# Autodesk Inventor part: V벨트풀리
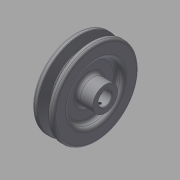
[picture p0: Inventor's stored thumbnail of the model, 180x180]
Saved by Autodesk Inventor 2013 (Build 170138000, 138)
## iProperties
Created: 2015-11
Part Number: V벨트풀리
Material: 강철, 탄소
Document SubType Name: Modeling
Designer: mduedu
Density: 1 g/cm^3
Author: mduedu
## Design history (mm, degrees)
sketch "스케치1"
  geometry: L1 (-9.5, 0)-(9.5, 0); L2 (0, 0)-(0, 37.7); L3 (-4.825, 37.7)-(-9.5, 37.7); L4 (-9.5, 37.7)-(-9.5, 0); L5 (0, 28.7)-(-2.074, 28.7); L6 (-2.074, 28.7)-(-4.825, 37.7); L7 (4.825, 37.7)-(9.5, 37.7); L8 (9.5, 37.7)-(9.5, 0); L9 (0, 28.7)-(2.074, 28.7); L10 (2.074, 28.7)-(4.825, 37.7); L11 (-9.5, 35)-(9.5, 35); 3 further points
  constraints: 22 end point, 7 point on line, 4 perpendicular, 3 symmetric about line, 1 coincident, 1 horizontal, 1 horizontal alignment, 1 midpoint, 1 vertical
  dimensions: "d0" = 19 distance of L1.start L1.end; "d2" = 75.4 diameter of L2.end L1 (derived); "d3" = 34 deg angle of L10 L6; "d4" = 6.3 distance between parallel lines of L11 L9; "d5" = 2.7 distance between parallel lines of L7 L11; "d6" = 8 distance of point (4, 35) point (-4, 35); "d7" = 70 diameter of L11 L1
revolve "회전1" sketch "스케치1" stored, may be unused: angle "d8" = 90 deg
sketch "스케치2"
  geometry: C1 r 24 at (0, 0); C2 r 11 at (0, 0); 1 further point
  constraints: 2 centre point, 2 coincident
  dimensions: "d9" = 48 diameter of C1; "d10" = 22 diameter of C2
extrude "돌출1" cut sketch "스케치2" distance "d11" = 6; taper "d12" = 0 deg
extrude "돌출3" join sketch "스케치2" distance "d37" = 8; taper "d38" = 0 deg
fillet "모깎기1" dims "d13" = 3
fillet "모깎기2" dims "d14" = 3
fillet "모깎기3" dims "d15" = 1, "d16" = 0.5, "d17" = 2
hole "구멍1" diameter "d20" = 12; stored, may be unused: countersink angle "d24" = 90 deg, drill point angle "d26" = 118 deg; dims "d21" = 6, "d22" = 4, "d23" = 2, "d25" = 8, "d58" = 10, "d59" = 10
sketch "스케치3"
  geometry: L1 (-2, 0)-(2, 0); L2 (2, 0)-(2, 7.8); L3 (2, 7.8)-(-2, 7.8); L4 (-2, 7.8)-(-2, 0); 2 further points
  constraints: 8 end point, 2 parallel, 1 coincident, 1 horizontal, 1 midpoint, 1 perpendicular
  dimensions: "d27" = 4 distance of L2.end L3.end; "d29" = 7.8 distance of L3.end L1.start
extrude "돌출2" cut sketch "스케치3" stored distance "d30" = 6; taper "d31" = 0 deg
node "작업 평면1"
sketch "스케치4"
  geometry: L1 (19, -27)-(19, 27) reference; 2 further points
  constraints: 1 horizontal alignment
  dimensions: "d52" = 22 distance from line of L1 point (-3, 0)
hole "구멍2" sketch "스케치4" at (-3, 0) diameter "d42" = 2.459; stored, may be unused: countersink angle "d46" = 90 deg, drill point angle "d48" = 118 deg; dims "d43" = 6, "d44" = 4, "d45" = 2, "d47" = 8
chamfer "모따기3" distance "d60" = 0.5; stored, may be unused: second distance "d61" = 2, angle "d62" = 45 deg
node "솔리드1"
mirror "대칭1"
